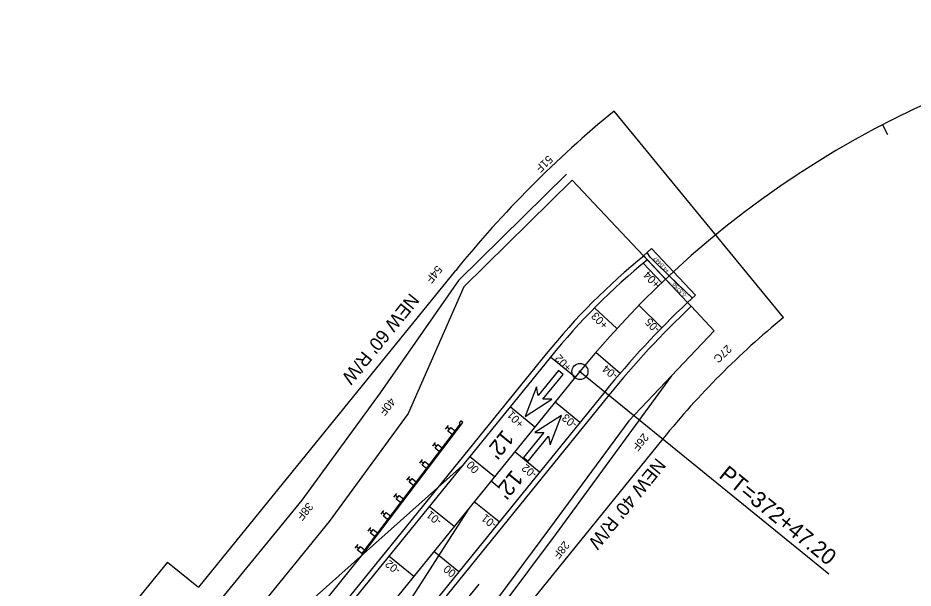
# Model space of a CAD drawing. Extents: x 144 to 1452322, y 4017 to 1128039.
# Drawn here: x 1450719.5 to 1451054.9, y 1127126.9 to 1127340.3 of the extents above; entities that cross this region are included whole.
import ezdxf

# ---------------------------------------------------------------- set-up
doc = ezdxf.new("R2010")
doc.units = 0
for name, color, linetype in [('RD_HC_Cl', 7, 'Continuous'), ('RD_HC_Data', 7, 'Continuous'), ('RD_HC_Data_Rel', 7, 'Continuous'), ('RD_HC_Data_Tic', 7, 'Continuous'), ('RD_PD_ALT1_TX', 7, 'Continuous'), ('RD_PD_CstnLmt', 7, 'Continuous'), ('RD_PD_CstnLmt_TX', 7, 'Continuous'), ('RD_PD_DR_ErosCtrl', 7, 'Continuous'), ('RD_PD_Final_TrvlWay', 7, 'Continuous'), ('RD_PD_Final_TX', 7, 'Continuous'), ('RD_PD_GR', 7, 'Continuous'), ('RD_PD_PaveShd', 7, 'Continuous'), ('RD_PD_RW', 7, 'Continuous'), ('RD_Sketch8', 7, 'Continuous'), ('RD_SMD_Locator', 7, 'Continuous'), ('RD_TX_Pipe_ElevEX', 7, 'Continuous')]:
    doc.layers.add(name, color=color, linetype=linetype)

msp = doc.modelspace()

# ---------------------------------------------------------------- linework, layer by layer
at = {"layer": 'RD_HC_Cl'}
msp.add_line((1450930.04, 1127207.93), (1450648.85, 1126861.73), dxfattribs=at)
msp.add_arc((1451208.01, 1126982.17), 358.1, 55.5264, 140.9167, dxfattribs=at)
at = {"layer": 'RD_HC_Data'}
msp.add_line((1450930.04, 1127207.93), (1451023.28, 1127132.2), dxfattribs=at)
for radius in [3, 0.282]:
    msp.add_circle((1450930.04, 1127207.93), radius, dxfattribs=at)
at = {"layer": 'RD_HC_Data_Rel'}
msp.add_line((1450831, 1127052.87), (1450892.33, 1127128.38), dxfattribs=at)
at = {"layer": 'RD_HC_Data_Tic'}
for p, q in [((1451043.41, 1127300.19), (1451045.24, 1127296.64)), ((1450962.12, 1127242.51), (1450964.87, 1127239.6)), ((1450896.75, 1127166.95), (1450899.86, 1127164.42))]:
    msp.add_line(p, q, dxfattribs=at)
at = {"layer": 'RD_PD_ALT1_TX'}
for p, q in [((1450960.67, 1127241.13), (1450953.71, 1127248.42)), ((1450943.88, 1127223.98), (1450935.45, 1127231.7)), ((1450960.71, 1127224.3), (1450952.13, 1127232.7)), ((1450945.05, 1127207.2), (1450935.93, 1127215)), ((1450928.27, 1127205.76), (1450918.96, 1127213.32)), ((1450913.14, 1127187.13), (1450903.83, 1127194.69)), ((1450930.02, 1127188.88), (1450920.71, 1127196.44)), ((1450914.89, 1127170.25), (1450905.58, 1127177.81)), ((1450898.01, 1127168.5), (1450888.7, 1127176.06)), ((1450882.88, 1127149.87), (1450873.57, 1127157.44)), ((1450899.76, 1127151.62), (1450890.45, 1127159.18)), ((1450884.63, 1127132.99), (1450875.32, 1127140.55)), ((1450867.75, 1127131.24), (1450858.44, 1127138.81))]:
    msp.add_line(p, q, dxfattribs=at)
at = {"layer": 'RD_PD_CstnLmt'}
for p, q in [((1450927.09, 1127279.6), (1450886.54, 1127239.66)), ((1450927.09, 1127279.6), (1450953.88, 1127251.23)), ((1450886.54, 1127239.66), (1450865.64, 1127192.22)), ((1450980.36, 1127223.2), (1450971.73, 1127232.33)), ((1450980.36, 1127223.2), (1450948.33, 1127189.47)), ((1450865.64, 1127192.22), (1450836.09, 1127151.8)), ((1450948.33, 1127189.47), (1450918.68, 1127149.14)), ((1450836.09, 1127151.8), (1450804.46, 1127113.08)), ((1450918.68, 1127149.14), (1450888.72, 1127109.06))]:
    msp.add_line(p, q, dxfattribs=at)
at = {"layer": 'RD_PD_DR_ErosCtrl'}
for p, q in [((1450924.98, 1127281.74), (1450884.58, 1127241.99)), ((1450884.58, 1127241.99), (1450855.15, 1127199.89)), ((1450964.34, 1127206.33), (1450950.75, 1127187.69)), ((1450855.15, 1127199.89), (1450825.8, 1127159.76)), ((1450950.75, 1127187.69), (1450921.09, 1127147.35)), ((1450825.8, 1127159.76), (1450794.49, 1127121.44)), ((1450921.09, 1127147.35), (1450891.29, 1127107.49))]:
    msp.add_line(p, q, dxfattribs=at)
at = {"layer": 'RD_PD_Final_TrvlWay'}
for p, q in [((1450970.36, 1127233.78), (1450955.3, 1127249.73)), ((1450918.96, 1127213.32), (1450785.44, 1127048.93)), ((1450939.35, 1127200.37), (1450800.02, 1127028.81))]:
    msp.add_line(p, q, dxfattribs=at)
for centre, radius, start in [((1451114.26, 1127054.7), 251.6, 129.1823), ((1451208.01, 1126982.17), 346.1, 133.3644)]:
    msp.add_arc(centre, radius, start, 140.9167, dxfattribs=at)
at = {"layer": 'RD_PD_Final_TX'}
for p, q in [((1450922, 1127208.25), (1450914.43, 1127198.93)), ((1450923.75, 1127206.83), (1450922, 1127208.25)), ((1450916.18, 1127197.52), (1450923.75, 1127206.83)), ((1450913.78, 1127202.17), (1450909.54, 1127191.12)), ((1450914.43, 1127198.93), (1450913.78, 1127202.17)), ((1450909.54, 1127191.12), (1450919.48, 1127197.54)), ((1450919.48, 1127197.54), (1450916.18, 1127197.52)), ((1450923.09, 1127191.5), (1450913.15, 1127185.08)), ((1450918.85, 1127180.45), (1450923.09, 1127191.5)), ((1450916.45, 1127185.1), (1450908.89, 1127175.79)), ((1450913.15, 1127185.08), (1450916.45, 1127185.1)), ((1450910.63, 1127174.37), (1450918.2, 1127183.69)), ((1450918.2, 1127183.69), (1450918.85, 1127180.45)), ((1450908.89, 1127175.79), (1450910.63, 1127174.37))]:
    msp.add_line(p, q, dxfattribs=at)
at = {"layer": 'RD_PD_GR'}
for p, q in [((1450885.21, 1127188.37), (1450848.3, 1127139.8)), ((1450848.69, 1127139.5), (1450886.21, 1127188.86)), ((1450880.65, 1127187.75), (1450879.59, 1127186.35)), ((1450885.41, 1127189.47), (1450884.81, 1127188.67)), ((1450884.81, 1127188.67), (1450885.2, 1127188.37)), ((1450886.21, 1127188.86), (1450885.41, 1127189.47)), ((1450881.12, 1127186.29), (1450880.12, 1127187.05)), ((1450880.59, 1127185.6), (1450881.65, 1127186.99)), ((1450882.18, 1127184.39), (1450880.59, 1127185.6)), ((1450881.65, 1127186.99), (1450883.24, 1127185.78)), ((1450883.24, 1127185.78), (1450882.18, 1127184.39)), ((1450875.81, 1127181.38), (1450874.75, 1127179.98)), ((1450876.28, 1127179.92), (1450875.28, 1127180.68)), ((1450875.75, 1127179.23), (1450876.81, 1127180.62)), ((1450876.81, 1127180.62), (1450878.4, 1127179.41)), ((1450877.34, 1127178.02), (1450875.75, 1127179.23)), ((1450878.4, 1127179.41), (1450877.34, 1127178.02)), ((1450870.97, 1127175.01), (1450869.91, 1127173.61)), ((1450871.44, 1127173.55), (1450870.44, 1127174.31)), ((1450870.91, 1127172.86), (1450871.97, 1127174.25)), ((1450871.97, 1127174.25), (1450873.56, 1127173.04)), ((1450872.5, 1127171.65), (1450870.91, 1127172.86)), ((1450873.56, 1127173.04), (1450872.5, 1127171.65)), ((1450866.13, 1127168.64), (1450865.07, 1127167.25)), ((1450866.6, 1127167.19), (1450865.6, 1127167.94)), ((1450866.07, 1127166.49), (1450867.13, 1127167.88)), ((1450867.13, 1127167.88), (1450868.72, 1127166.67)), ((1450867.66, 1127165.28), (1450866.07, 1127166.49)), ((1450868.72, 1127166.67), (1450867.66, 1127165.28)), ((1450861.29, 1127162.27), (1450860.23, 1127160.88)), ((1450861.75, 1127160.82), (1450860.76, 1127161.57)), ((1450861.23, 1127160.12), (1450862.28, 1127161.51)), ((1450862.28, 1127161.51), (1450863.88, 1127160.3)), ((1450862.82, 1127158.91), (1450861.23, 1127160.12)), ((1450863.88, 1127160.3), (1450862.82, 1127158.91)), ((1450856.45, 1127155.9), (1450855.39, 1127154.51)), ((1450856.91, 1127154.45), (1450855.92, 1127155.2)), ((1450856.38, 1127153.75), (1450857.44, 1127155.14)), ((1450857.44, 1127155.14), (1450859.04, 1127153.93)), ((1450859.04, 1127153.93), (1450857.98, 1127152.54)), ((1450857.98, 1127152.54), (1450856.38, 1127153.75)), ((1450851.61, 1127149.53), (1450850.55, 1127148.14)), ((1450852.07, 1127148.08), (1450851.08, 1127148.83)), ((1450851.54, 1127147.38), (1450852.6, 1127148.77)), ((1450853.14, 1127146.17), (1450851.54, 1127147.38)), ((1450852.6, 1127148.77), (1450854.2, 1127147.56)), ((1450854.2, 1127147.56), (1450853.14, 1127146.17)), ((1450846.77, 1127143.16), (1450845.71, 1127141.77)), ((1450847.23, 1127141.71), (1450846.24, 1127142.47)), ((1450846.7, 1127141.01), (1450847.76, 1127142.41)), ((1450848.3, 1127139.8), (1450846.7, 1127141.01)), ((1450847.76, 1127142.41), (1450849.35, 1127141.2)), ((1450849.35, 1127141.2), (1450848.3, 1127139.8)), ((1450803.89, 1127084.34), (1450848.69, 1127139.5)), ((1450848.3, 1127139.8), (1450848.69, 1127139.5))]:
    msp.add_line(p, q, dxfattribs=at)
at = {"layer": 'RD_PD_PaveShd'}
for p, q in [((1450955.3, 1127249.73), (1450953.93, 1127251.18)), ((1450970.36, 1127233.78), (1450971.73, 1127232.33)), ((1450917.41, 1127214.58), (1450825.07, 1127100.9)), ((1450940.91, 1127199.1), (1450829.02, 1127061.35))]:
    msp.add_line(p, q, dxfattribs=at)
for centre, radius, start in [((1451114.26, 1127054.7), 253.6, 129.1823), ((1451208.01, 1126982.17), 344.1, 133.3644)]:
    msp.add_arc(centre, radius, start, 140.9167, dxfattribs=at)
at = {"layer": 'RD_PD_RW'}
for p, q in [((1451006.25, 1127228.1), (1450942.83, 1127305.41)), ((1450883.46, 1127245.76), (1450787.13, 1127127.15)), ((1450961.09, 1127182.71), (1450896.53, 1127103.23)), ((1450775.49, 1127136.61), (1450590.64, 1126909.01)), ((1450775.49, 1127136.61), (1450787.13, 1127127.15))]:
    msp.add_line(p, q, dxfattribs=at)
for radius in [418.1, 318.1]:
    msp.add_arc((1451208.01, 1126982.17), radius, 129.3644, 140.9167, dxfattribs=at)
at = {"layer": 'RD_Sketch8'}
for p, q in [((1450764.89, 1127064.86), (1450885.94, 1127172.67)), ((1450888.34, 1127156.59), (1450801.44, 1127021.05))]:
    msp.add_line(p, q, dxfattribs=at)
at = {"layer": 'RD_SMD_Locator'}
msp.add_circle((1450930.04, 1127207.93), 0.15, dxfattribs=at)
at = {"layer": 'RD_TX_Pipe_ElevEX'}
for q in [(1450956.29, 1127250.66), (1450972.13, 1127235.45)]:
    msp.add_line((1450963.4, 1127243.71), q, dxfattribs=at)
msp.add_lwpolyline([(1450973.27, 1127236.53), (1450970.36, 1127233.78), (1450953.88, 1127251.23), (1450956.79, 1127253.98)], close=True, dxfattribs=at)
msp.add_lwpolyline([(1450972.13, 1127235.45), (1450965.86, 1127241.36), (1450964.58, 1127242.56), (1450957.03, 1127249.94), (1450956.29, 1127250.66), (1450955.19, 1127252.47)], dxfattribs=at)

# ---------------------------------------------------------------- texts
at = {"layer": 'RD_HC_Data'}
msp.add_text('PT=372+47.20', height=6, rotation=320.9167, dxfattribs=at).set_placement((1450981.75, 1127168.5))
at = {"layer": 'RD_PD_ALT1_TX'}
for s, rotation, p in [('+04', 133.3644, (1450960.35, 1127240.85)), ('+03', 133.3644, (1450940.82, 1127225.49)), ('-05', 133.3644, (1450960.26, 1127224.03)), ('+02', 133.3644, (1450927.17, 1127209.63)), ('-04', 140.9167, (1450944.47, 1127206.96)), ('+01', 133.3644, (1450909.27, 1127188.57)), ('-03', 140.9167, (1450929.32, 1127188.66)), ('00', 133.3644, (1450892.5, 1127171.49)), ('-02', 140.9167, (1450914.27, 1127169.92)), ('-01', 140.9167, (1450878.52, 1127152.36)), ('-01', 140.9167, (1450899.14, 1127151.14)), ('-02', 140.9167, (1450863.1, 1127133.98)), ('00', 140.9167, (1450883.88, 1127132.91))]:
    msp.add_text(s, height=3, rotation=rotation, dxfattribs=at).set_placement(p)
at = {"layer": 'RD_PD_CstnLmt_TX'}
for s, rotation, p in [('51F', 223.3644, (1450918.16, 1127289.05)), ('54F', 230.9167, (1450876.44, 1127247.85)), ('27C', 223.3644, (1450985.16, 1127218.11)), ('40F', 230.9167, (1450858.91, 1127198.37)), ('26F', 230.9167, (1450953.76, 1127185.06)), ('38F', 230.9167, (1450828.05, 1127159.11)), ('28F', 230.9167, (1450924.11, 1127144.72))]:
    msp.add_text(s, height=3, rotation=rotation, dxfattribs=at).set_placement(p)
at = {"layer": 'RD_PD_Final_TX'}
for p in [(1450901.23, 1127186.52), (1450904.67, 1127171.49)]:
    msp.add_text("12'", height=6, rotation=230.9173, dxfattribs=at).set_placement(p)
at = {"layer": 'RD_PD_RW'}
for s, p in [("NEW 60' R/W", (1450866.35, 1127237.64)), ("NEW 40' R/W", (1450958.73, 1127175.88))]:
    msp.add_text(s, height=5, rotation=230.9167, dxfattribs=at).set_placement(p)
at = {"layer": 'RD_TX_Pipe_ElevEX'}
for s, p in [('+4.0447', (1450963.68, 1127245.65)), ('-5.5750', (1450970.41, 1127236.36))]:
    msp.add_text(s, height=1.5, rotation=133.3644, dxfattribs=at).set_placement(p)

doc.saveas('drawing.dxf')
